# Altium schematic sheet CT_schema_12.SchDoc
size 390 x 385 mm
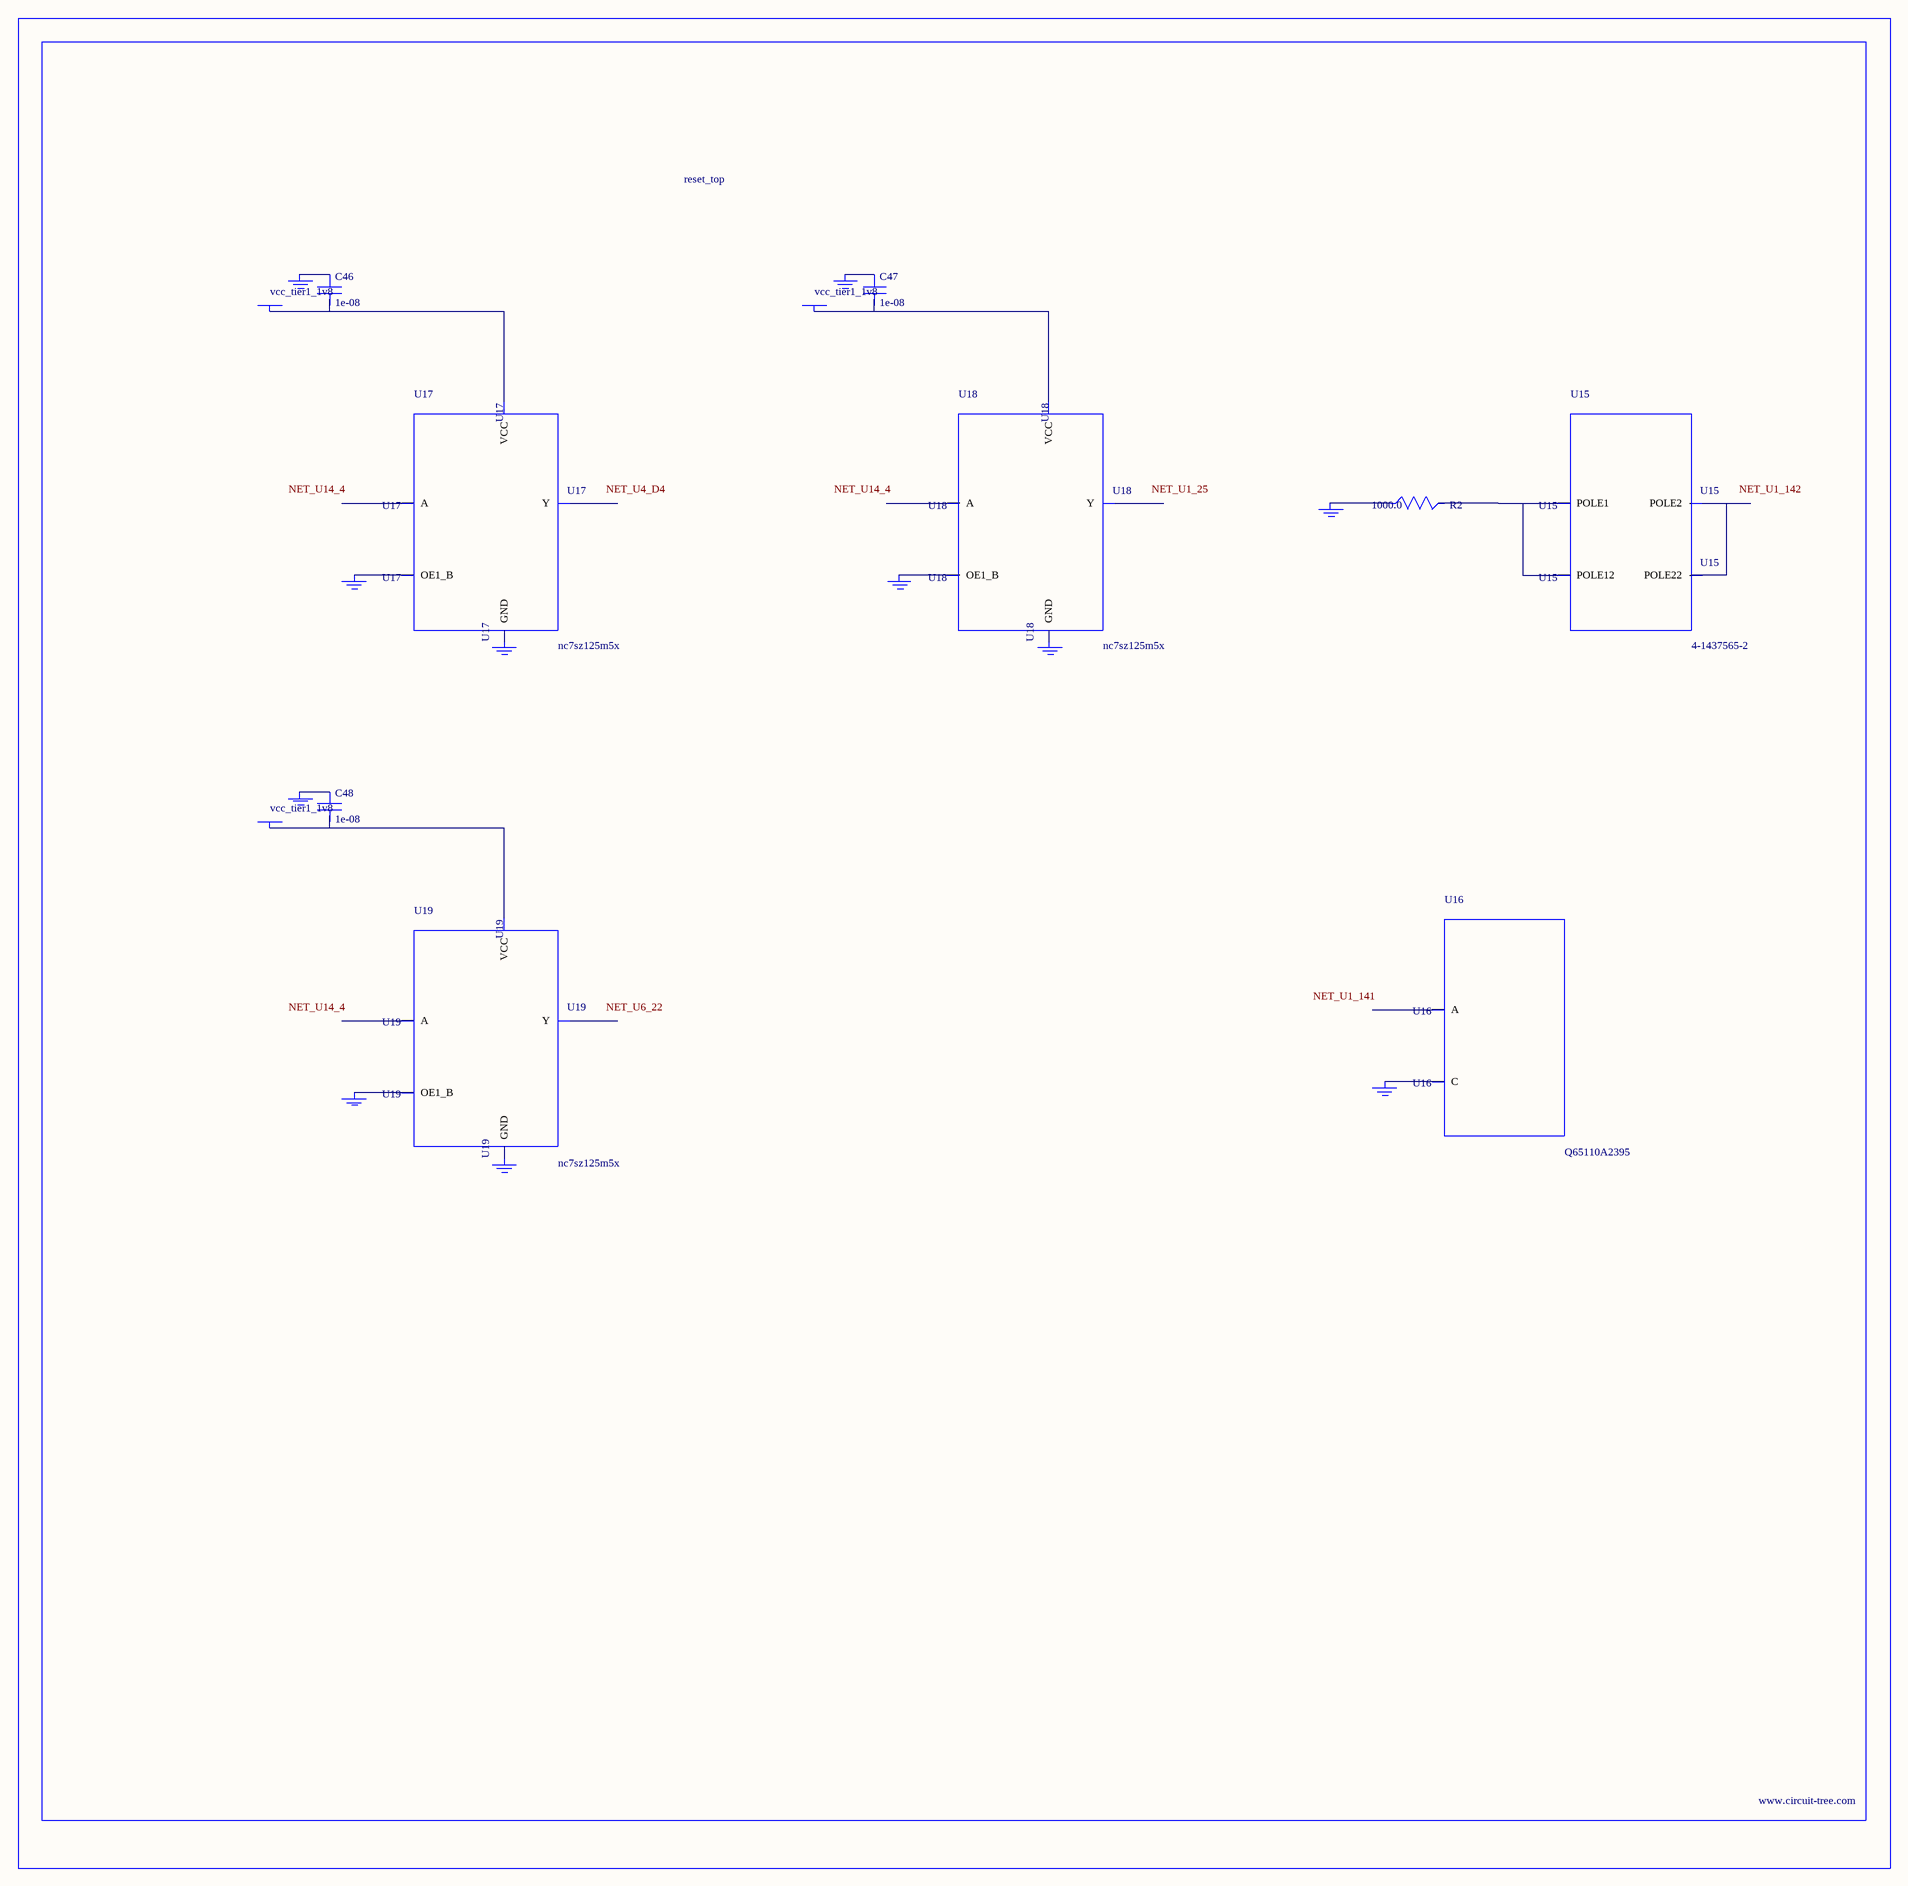
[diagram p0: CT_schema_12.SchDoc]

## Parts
BORDER11  (no value)
C46  1e-08  [C0402]
C47  1e-08  [C0402]
C48  1e-08  [C0402]
GND_INSTANCE_11_0  (no value)
GND_INSTANCE_11_1  (no value)
GND_INSTANCE_11_2  (no value)
GND_INSTANCE_11_3  (no value)
GND_INSTANCE_11_4  (no value)
GND_INSTANCE_11_5  (no value)
GND_INSTANCE_11_6  (no value)
GND_INSTANCE_11_7  (no value)
GND_INSTANCE_11_8  (no value)
GND_INSTANCE_11_9  (no value)
GND_INSTANCE_11_10  (no value)
POWER_INSTANCE_11_0  vcc_tier1_1v8
POWER_INSTANCE_11_1  vcc_tier1_1v8
POWER_INSTANCE_11_2  vcc_tier1_1v8
R2  1000.0  [R0603]
U15  4-1437565-2  [SW_4-1437565-2]
U16  Q65110A2395  [LGM67K-G1J2-24-Z]
U17  nc7sz125m5x  [NC7SZ125M5X]
U18  nc7sz125m5x  [NC7SZ125M5X]
U19  nc7sz125m5x  [NC7SZ125M5X]

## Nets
NetC46_1: C46.1 GND_INSTANCE_11_2.0(GND)
NetC46_2: C46.2 POWER_INSTANCE_11_0.0(PWR) U17.5(VCC)
NetC47_1: C47.1 GND_INSTANCE_11_5.0(GND)
NetC47_2: C47.2 POWER_INSTANCE_11_1.0(PWR) U18.5(VCC)
NetC48_1: C48.1 GND_INSTANCE_11_8.0(GND)
NetC48_2: C48.2 POWER_INSTANCE_11_2.0(PWR) U19.5(VCC)
NetGND_INSTANCE_11_0_0: GND_INSTANCE_11_0.0(GND) R2.1
NetGND_INSTANCE_11_1_0: GND_INSTANCE_11_1.0(GND) U16.C
NetGND_INSTANCE_11_3_0: GND_INSTANCE_11_3.0(GND) U17.1(OE1_B)
NetGND_INSTANCE_11_4_0: GND_INSTANCE_11_4.0(GND) U17.3(GND)
NetGND_INSTANCE_11_6_0: GND_INSTANCE_11_6.0(GND) U18.1(OE1_B)
NetGND_INSTANCE_11_7_0: GND_INSTANCE_11_7.0(GND) U18.3(GND)
NetGND_INSTANCE_11_9_0: GND_INSTANCE_11_9.0(GND) U19.1(OE1_B)
NetGND_INSTANCE_11_10_0: GND_INSTANCE_11_10.0(GND) U19.3(GND)
NetR2_2: R2.2 U15.1(POLE1) U15.2(POLE12)
NetU15_3: U15.3(POLE2) U15.4(POLE22)

Not connected (* = marked no-connect by the designer): U16 A; U17 2(A) 4(Y); U18 2(A) 4(Y); U19 2(A) 4(Y)

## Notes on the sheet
- Labels drawn without touching a wire or pin: NET_U1_25, NET_U1_141, NET_U1_142, NET_U4_D4, NET_U6_22, NET_U14_4

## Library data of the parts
BORDER11 = BORDER_PAGE11
C46-C48 = C0402C103K3RAC
GND_INSTANCE_11_0-GND_INSTANCE_11_10 = GND
POWER_INSTANCE_11_0-POWER_INSTANCE_11_2 = PWR
R2 = RC0603JR-071KL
